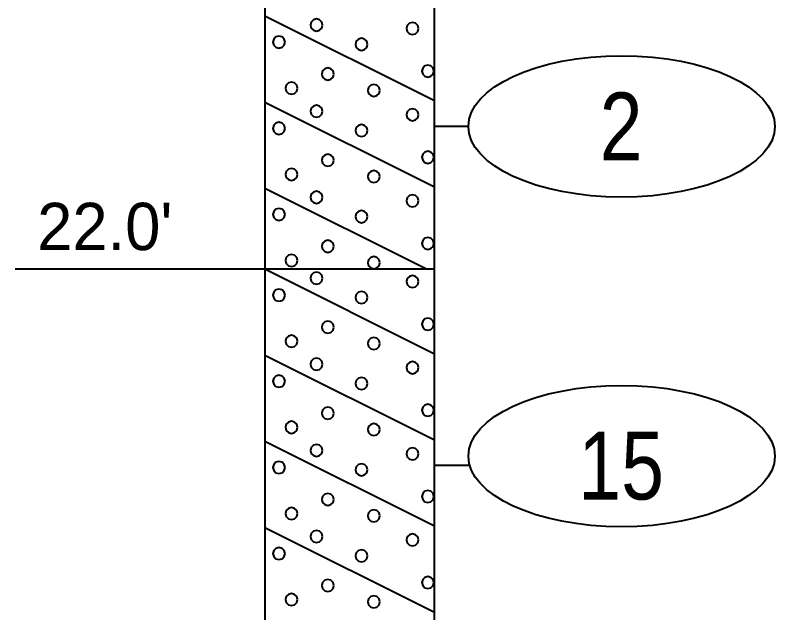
# Model space of a CAD drawing. Extents: x -76 to 974, y -1080 to -735.
# Drawn here: x -15.21 to -4.02, y -793.08 to -784.27 of the extents above; entities that cross this region are included whole.
import ezdxf
from ezdxf.enums import TextEntityAlignment as Align

# ---------------------------------------------------------------- set-up
doc = ezdxf.new("R2010")
doc.units = 0
doc.header["$LTSCALE"] = 0.36
doc.layers.add('27', color=7, linetype='Continuous', lineweight=40)

msp = doc.modelspace()

# ---------------------------------------------------------------- linework, layer by layer
at = {"layer": '27'}
for p, q in [((-11.5338, -783.0053), (-11.5338, -788.0053)), ((-9.0338, -788.0053), (-9.0338, -783.0053)), ((-11.5338, -784.2753), (-9.0338, -785.5253)), ((-11.5338, -785.5453), (-9.0338, -786.7953)), ((-8.5338, -785.9053), (-9.0338, -785.9053)), ((-11.5338, -786.8153), (-9.1538, -788.0053)), ((-15.2122, -788.0053), (-11.4448, -788.0053)), ((-11.5338, -788.0053), (-9.0338, -788.0053)), ((-11.5338, -788.0053), (-9.0338, -789.2553)), ((-11.5338, -788.0053), (-11.5338, -798.0053)), ((-9.0338, -798.0053), (-9.0338, -788.0053)), ((-11.5338, -789.2753), (-9.0338, -790.5253)), ((-11.5338, -790.5453), (-9.0338, -791.7953)), ((-8.5338, -790.9053), (-9.0338, -790.9053)), ((-11.5338, -791.8153), (-9.0338, -793.0653))]:
    msp.add_line(p, q, dxfattribs=at)
for points in [[(-10.6832, -784.4104), (-10.6951, -784.366), (-10.7276, -784.3334), (-10.7721, -784.3215), (-10.8165, -784.3334), (-10.849, -784.366), (-10.861, -784.4104), (-10.849, -784.4549), (-10.8165, -784.4874), (-10.7721, -784.4993), (-10.7276, -784.4874), (-10.6951, -784.4549)], [(-9.2682, -784.4613), (-9.2801, -784.4168), (-9.3127, -784.3843), (-9.3571, -784.3724), (-9.4016, -784.3843), (-9.4341, -784.4168), (-9.446, -784.4613), (-9.4341, -784.5057), (-9.4016, -784.5383), (-9.3571, -784.5502), (-9.3127, -784.5383), (-9.2801, -784.5057)], [(-11.2362, -784.6621), (-11.2481, -784.6177), (-11.2806, -784.5851), (-11.3251, -784.5732), (-11.3695, -784.5851), (-11.4021, -784.6177), (-11.414, -784.6621), (-11.4021, -784.7066), (-11.3695, -784.7391), (-11.3251, -784.751), (-11.2806, -784.7391), (-11.2481, -784.7066)], [(-10.0208, -784.6952), (-10.0327, -784.6507), (-10.0653, -784.6182), (-10.1097, -784.6063), (-10.1542, -784.6182), (-10.1867, -784.6507), (-10.1986, -784.6952), (-10.1867, -784.7396), (-10.1542, -784.7722), (-10.1097, -784.7841), (-10.0653, -784.7722), (-10.0327, -784.7396)], [(-10.5166, -785.1325), (-10.5285, -785.088), (-10.5611, -785.0555), (-10.6055, -785.0436), (-10.65, -785.0555), (-10.6825, -785.088), (-10.6944, -785.1325), (-10.6825, -785.1769), (-10.65, -785.2095), (-10.6055, -785.2214), (-10.5611, -785.2095), (-10.5285, -785.1769)], [(-9.0419, -785.0893), (-9.0539, -785.0448), (-9.0864, -785.0123), (-9.1308, -785.0004), (-9.1753, -785.0123), (-9.2078, -785.0448), (-9.2197, -785.0893), (-9.2078, -785.1337), (-9.1753, -785.1663), (-9.1308, -785.1782), (-9.0864, -785.1663), (-9.0539, -785.1337)], [(-11.0518, -785.341), (-11.0637, -785.2965), (-11.0963, -785.264), (-11.1407, -785.2521), (-11.1852, -785.264), (-11.2177, -785.2965), (-11.2296, -785.341), (-11.2177, -785.3854), (-11.1852, -785.418), (-11.1407, -785.4299), (-11.0963, -785.418), (-11.0637, -785.3854)], [(-9.839, -785.374), (-9.8509, -785.3296), (-9.8835, -785.297), (-9.9279, -785.2851), (-9.9724, -785.297), (-10.0049, -785.3296), (-10.0168, -785.374), (-10.0049, -785.4185), (-9.9724, -785.451), (-9.9279, -785.4629), (-9.8835, -785.451), (-9.8509, -785.4185)], [(-10.6831, -785.6816), (-10.695, -785.6372), (-10.7275, -785.6046), (-10.772, -785.5927), (-10.8164, -785.6046), (-10.849, -785.6372), (-10.8609, -785.6816), (-10.849, -785.7261), (-10.8164, -785.7586), (-10.772, -785.7705), (-10.7275, -785.7586), (-10.695, -785.7261)], [(-9.2682, -785.7325), (-9.2801, -785.6881), (-9.3127, -785.6555), (-9.3571, -785.6436), (-9.4016, -785.6555), (-9.4341, -785.6881), (-9.446, -785.7325), (-9.4341, -785.777), (-9.4016, -785.8095), (-9.3571, -785.8214), (-9.3127, -785.8095), (-9.2801, -785.777)], [(-11.2362, -785.9334), (-11.2481, -785.8889), (-11.2806, -785.8564), (-11.3251, -785.8445), (-11.3695, -785.8564), (-11.4021, -785.8889), (-11.414, -785.9334), (-11.4021, -785.9778), (-11.3695, -786.0104), (-11.3251, -786.0223), (-11.2806, -786.0104), (-11.2481, -785.9778)], [(-10.0208, -785.9664), (-10.0327, -785.922), (-10.0653, -785.8895), (-10.1097, -785.8775), (-10.1542, -785.8895), (-10.1867, -785.922), (-10.1986, -785.9664), (-10.1867, -786.0109), (-10.1542, -786.0434), (-10.1097, -786.0553), (-10.0653, -786.0434), (-10.0327, -786.0109)], [(-10.5166, -786.4038), (-10.5285, -786.3593), (-10.5611, -786.3268), (-10.6055, -786.3149), (-10.65, -786.3268), (-10.6825, -786.3593), (-10.6944, -786.4038), (-10.6825, -786.4482), (-10.65, -786.4808), (-10.6055, -786.4927), (-10.5611, -786.4808), (-10.5285, -786.4482)], [(-9.0419, -786.3605), (-9.0539, -786.3161), (-9.0864, -786.2836), (-9.1308, -786.2716), (-9.1753, -786.2836), (-9.2078, -786.3161), (-9.2197, -786.3605), (-9.2078, -786.405), (-9.1753, -786.4375), (-9.1308, -786.4494), (-9.0864, -786.4375), (-9.0539, -786.405)], [(-11.0518, -786.6123), (-11.0637, -786.5678), (-11.0963, -786.5353), (-11.1407, -786.5234), (-11.1852, -786.5353), (-11.2177, -786.5678), (-11.2296, -786.6123), (-11.2177, -786.6567), (-11.1852, -786.6892), (-11.1407, -786.7012), (-11.0963, -786.6892), (-11.0637, -786.6567)], [(-9.839, -786.6453), (-9.8509, -786.6009), (-9.8835, -786.5683), (-9.9279, -786.5564), (-9.9724, -786.5683), (-10.0049, -786.6009), (-10.0168, -786.6453), (-10.0049, -786.6898), (-9.9724, -786.7223), (-9.9279, -786.7342), (-9.8835, -786.7223), (-9.8509, -786.6898)], [(-10.6832, -786.9504), (-10.6951, -786.906), (-10.7276, -786.8734), (-10.7721, -786.8615), (-10.8165, -786.8734), (-10.849, -786.906), (-10.861, -786.9504), (-10.849, -786.9949), (-10.8165, -787.0274), (-10.7721, -787.0393), (-10.7276, -787.0274), (-10.6951, -786.9949)], [(-9.2682, -787.0013), (-9.2801, -786.9568), (-9.3127, -786.9243), (-9.3571, -786.9124), (-9.4016, -786.9243), (-9.4341, -786.9568), (-9.446, -787.0013), (-9.4341, -787.0457), (-9.4016, -787.0783), (-9.3571, -787.0902), (-9.3127, -787.0783), (-9.2801, -787.0457)], [(-11.2362, -787.2021), (-11.2481, -787.1577), (-11.2806, -787.1251), (-11.3251, -787.1132), (-11.3695, -787.1251), (-11.4021, -787.1577), (-11.414, -787.2021), (-11.4021, -787.2466), (-11.3695, -787.2791), (-11.3251, -787.291), (-11.2806, -787.2791), (-11.2481, -787.2466)], [(-10.0208, -787.2352), (-10.0327, -787.1907), (-10.0653, -787.1582), (-10.1097, -787.1463), (-10.1542, -787.1582), (-10.1867, -787.1907), (-10.1986, -787.2352), (-10.1867, -787.2796), (-10.1542, -787.3122), (-10.1097, -787.3241), (-10.0653, -787.3122), (-10.0327, -787.2796)], [(-9.0419, -787.6293), (-9.0539, -787.5848), (-9.0864, -787.5523), (-9.1308, -787.5404), (-9.1753, -787.5523), (-9.2078, -787.5848), (-9.2197, -787.6293), (-9.2078, -787.6737), (-9.1753, -787.7063), (-9.1308, -787.7182), (-9.0864, -787.7063), (-9.0539, -787.6737)], [(-10.5166, -787.6725), (-10.5285, -787.628), (-10.5611, -787.5955), (-10.6055, -787.5836), (-10.65, -787.5955), (-10.6825, -787.628), (-10.6944, -787.6725), (-10.6825, -787.7169), (-10.65, -787.7495), (-10.6055, -787.7614), (-10.5611, -787.7495), (-10.5285, -787.7169)], [(-11.0518, -787.881), (-11.0637, -787.8365), (-11.0963, -787.804), (-11.1407, -787.7921), (-11.1852, -787.804), (-11.2177, -787.8365), (-11.2296, -787.881), (-11.2177, -787.9254), (-11.1852, -787.958), (-11.1407, -787.9699), (-11.0963, -787.958), (-11.0637, -787.9254)], [(-9.839, -787.914), (-9.8509, -787.8696), (-9.8835, -787.837), (-9.9279, -787.8251), (-9.9724, -787.837), (-10.0049, -787.8696), (-10.0168, -787.914), (-10.0049, -787.9585), (-9.9724, -787.991), (-9.9279, -788.0029), (-9.8835, -787.991), (-9.8509, -787.9585)], [(-10.6831, -788.1416), (-10.695, -788.0972), (-10.7275, -788.0646), (-10.772, -788.0527), (-10.8164, -788.0646), (-10.849, -788.0972), (-10.8609, -788.1416), (-10.849, -788.1861), (-10.8164, -788.2186), (-10.772, -788.2305), (-10.7275, -788.2186), (-10.695, -788.1861)], [(-9.2682, -788.1925), (-9.2801, -788.1481), (-9.3127, -788.1155), (-9.3571, -788.1036), (-9.4016, -788.1155), (-9.4341, -788.1481), (-9.446, -788.1925), (-9.4341, -788.237), (-9.4016, -788.2695), (-9.3571, -788.2814), (-9.3127, -788.2695), (-9.2801, -788.237)], [(-11.2362, -788.3934), (-11.2481, -788.3489), (-11.2806, -788.3164), (-11.3251, -788.3045), (-11.3695, -788.3164), (-11.4021, -788.3489), (-11.414, -788.3934), (-11.4021, -788.4378), (-11.3695, -788.4704), (-11.3251, -788.4823), (-11.2806, -788.4704), (-11.2481, -788.4378)], [(-10.0208, -788.4264), (-10.0327, -788.382), (-10.0653, -788.3495), (-10.1097, -788.3375), (-10.1542, -788.3495), (-10.1867, -788.382), (-10.1986, -788.4264), (-10.1867, -788.4709), (-10.1542, -788.5034), (-10.1097, -788.5153), (-10.0653, -788.5034), (-10.0327, -788.4709)], [(-10.5166, -788.8638), (-10.5285, -788.8193), (-10.5611, -788.7868), (-10.6055, -788.7749), (-10.65, -788.7868), (-10.6825, -788.8193), (-10.6944, -788.8638), (-10.6825, -788.9082), (-10.65, -788.9408), (-10.6055, -788.9527), (-10.5611, -788.9408), (-10.5285, -788.9082)], [(-9.0419, -788.8205), (-9.0539, -788.7761), (-9.0864, -788.7436), (-9.1308, -788.7316), (-9.1753, -788.7436), (-9.2078, -788.7761), (-9.2197, -788.8205), (-9.2078, -788.865), (-9.1753, -788.8975), (-9.1308, -788.9094), (-9.0864, -788.8975), (-9.0539, -788.865)], [(-11.0518, -789.0723), (-11.0637, -789.0278), (-11.0963, -788.9953), (-11.1407, -788.9834), (-11.1852, -788.9953), (-11.2177, -789.0278), (-11.2296, -789.0723), (-11.2177, -789.1167), (-11.1852, -789.1492), (-11.1407, -789.1612), (-11.0963, -789.1492), (-11.0637, -789.1167)], [(-9.839, -789.1053), (-9.8509, -789.0609), (-9.8835, -789.0283), (-9.9279, -789.0164), (-9.9724, -789.0283), (-10.0049, -789.0609), (-10.0168, -789.1053), (-10.0049, -789.1498), (-9.9724, -789.1823), (-9.9279, -789.1942), (-9.8835, -789.1823), (-9.8509, -789.1498)], [(-10.6832, -789.4104), (-10.6951, -789.366), (-10.7276, -789.3334), (-10.7721, -789.3215), (-10.8165, -789.3334), (-10.849, -789.366), (-10.861, -789.4104), (-10.849, -789.4549), (-10.8165, -789.4874), (-10.7721, -789.4993), (-10.7276, -789.4874), (-10.6951, -789.4549)], [(-9.2682, -789.4613), (-9.2801, -789.4168), (-9.3127, -789.3843), (-9.3571, -789.3724), (-9.4016, -789.3843), (-9.4341, -789.4168), (-9.446, -789.4613), (-9.4341, -789.5057), (-9.4016, -789.5383), (-9.3571, -789.5502), (-9.3127, -789.5383), (-9.2801, -789.5057)], [(-11.2362, -789.6621), (-11.2481, -789.6177), (-11.2806, -789.5851), (-11.3251, -789.5732), (-11.3695, -789.5851), (-11.4021, -789.6177), (-11.414, -789.6621), (-11.4021, -789.7066), (-11.3695, -789.7391), (-11.3251, -789.751), (-11.2806, -789.7391), (-11.2481, -789.7066)], [(-10.0208, -789.6952), (-10.0327, -789.6507), (-10.0653, -789.6182), (-10.1097, -789.6063), (-10.1542, -789.6182), (-10.1867, -789.6507), (-10.1986, -789.6952), (-10.1867, -789.7396), (-10.1542, -789.7722), (-10.1097, -789.7841), (-10.0653, -789.7722), (-10.0327, -789.7396)], [(-9.0419, -790.0893), (-9.0539, -790.0448), (-9.0864, -790.0123), (-9.1308, -790.0004), (-9.1753, -790.0123), (-9.2078, -790.0448), (-9.2197, -790.0893), (-9.2078, -790.1337), (-9.1753, -790.1663), (-9.1308, -790.1782), (-9.0864, -790.1663), (-9.0539, -790.1337)], [(-10.5166, -790.1325), (-10.5285, -790.088), (-10.5611, -790.0555), (-10.6055, -790.0436), (-10.65, -790.0555), (-10.6825, -790.088), (-10.6944, -790.1325), (-10.6825, -790.1769), (-10.65, -790.2095), (-10.6055, -790.2214), (-10.5611, -790.2095), (-10.5285, -790.1769)], [(-11.0518, -790.341), (-11.0637, -790.2965), (-11.0963, -790.264), (-11.1407, -790.2521), (-11.1852, -790.264), (-11.2177, -790.2965), (-11.2296, -790.341), (-11.2177, -790.3854), (-11.1852, -790.418), (-11.1407, -790.4299), (-11.0963, -790.418), (-11.0637, -790.3854)], [(-9.839, -790.374), (-9.8509, -790.3296), (-9.8835, -790.297), (-9.9279, -790.2851), (-9.9724, -790.297), (-10.0049, -790.3296), (-10.0168, -790.374), (-10.0049, -790.4185), (-9.9724, -790.451), (-9.9279, -790.4629), (-9.8835, -790.451), (-9.8509, -790.4185)], [(-10.6831, -790.6816), (-10.695, -790.6372), (-10.7275, -790.6046), (-10.772, -790.5927), (-10.8164, -790.6046), (-10.849, -790.6372), (-10.8609, -790.6816), (-10.849, -790.7261), (-10.8164, -790.7586), (-10.772, -790.7705), (-10.7275, -790.7586), (-10.695, -790.7261)], [(-9.2682, -790.7325), (-9.2801, -790.6881), (-9.3127, -790.6555), (-9.3571, -790.6436), (-9.4016, -790.6555), (-9.4341, -790.6881), (-9.446, -790.7325), (-9.4341, -790.777), (-9.4016, -790.8095), (-9.3571, -790.8214), (-9.3127, -790.8095), (-9.2801, -790.777)], [(-11.2362, -790.9334), (-11.2481, -790.8889), (-11.2806, -790.8564), (-11.3251, -790.8445), (-11.3695, -790.8564), (-11.4021, -790.8889), (-11.414, -790.9334), (-11.4021, -790.9778), (-11.3695, -791.0104), (-11.3251, -791.0223), (-11.2806, -791.0104), (-11.2481, -790.9778)], [(-10.0208, -790.9664), (-10.0327, -790.922), (-10.0653, -790.8895), (-10.1097, -790.8775), (-10.1542, -790.8895), (-10.1867, -790.922), (-10.1986, -790.9664), (-10.1867, -791.0109), (-10.1542, -791.0434), (-10.1097, -791.0553), (-10.0653, -791.0434), (-10.0327, -791.0109)], [(-10.5166, -791.4038), (-10.5285, -791.3593), (-10.5611, -791.3268), (-10.6055, -791.3149), (-10.65, -791.3268), (-10.6825, -791.3593), (-10.6944, -791.4038), (-10.6825, -791.4482), (-10.65, -791.4808), (-10.6055, -791.4927), (-10.5611, -791.4808), (-10.5285, -791.4482)], [(-9.0419, -791.3605), (-9.0539, -791.3161), (-9.0864, -791.2836), (-9.1308, -791.2716), (-9.1753, -791.2836), (-9.2078, -791.3161), (-9.2197, -791.3605), (-9.2078, -791.405), (-9.1753, -791.4375), (-9.1308, -791.4494), (-9.0864, -791.4375), (-9.0539, -791.405)], [(-11.0518, -791.6123), (-11.0637, -791.5678), (-11.0963, -791.5353), (-11.1407, -791.5234), (-11.1852, -791.5353), (-11.2177, -791.5678), (-11.2296, -791.6123), (-11.2177, -791.6567), (-11.1852, -791.6892), (-11.1407, -791.7012), (-11.0963, -791.6892), (-11.0637, -791.6567)], [(-9.839, -791.6453), (-9.8509, -791.6009), (-9.8835, -791.5683), (-9.9279, -791.5564), (-9.9724, -791.5683), (-10.0049, -791.6009), (-10.0168, -791.6453), (-10.0049, -791.6898), (-9.9724, -791.7223), (-9.9279, -791.7342), (-9.8835, -791.7223), (-9.8509, -791.6898)], [(-10.6832, -791.9504), (-10.6951, -791.906), (-10.7276, -791.8734), (-10.7721, -791.8615), (-10.8165, -791.8734), (-10.849, -791.906), (-10.861, -791.9504), (-10.849, -791.9949), (-10.8165, -792.0274), (-10.7721, -792.0393), (-10.7276, -792.0274), (-10.6951, -791.9949)], [(-9.2682, -792.0013), (-9.2801, -791.9568), (-9.3127, -791.9243), (-9.3571, -791.9124), (-9.4016, -791.9243), (-9.4341, -791.9568), (-9.446, -792.0013), (-9.4341, -792.0457), (-9.4016, -792.0783), (-9.3571, -792.0902), (-9.3127, -792.0783), (-9.2801, -792.0457)], [(-11.2362, -792.2021), (-11.2481, -792.1577), (-11.2806, -792.1251), (-11.3251, -792.1132), (-11.3695, -792.1251), (-11.4021, -792.1577), (-11.414, -792.2021), (-11.4021, -792.2466), (-11.3695, -792.2791), (-11.3251, -792.291), (-11.2806, -792.2791), (-11.2481, -792.2466)], [(-10.0208, -792.2352), (-10.0327, -792.1907), (-10.0653, -792.1582), (-10.1097, -792.1463), (-10.1542, -792.1582), (-10.1867, -792.1907), (-10.1986, -792.2352), (-10.1867, -792.2796), (-10.1542, -792.3122), (-10.1097, -792.3241), (-10.0653, -792.3122), (-10.0327, -792.2796)], [(-10.5166, -792.6725), (-10.5285, -792.628), (-10.5611, -792.5955), (-10.6055, -792.5836), (-10.65, -792.5955), (-10.6825, -792.628), (-10.6944, -792.6725), (-10.6825, -792.7169), (-10.65, -792.7495), (-10.6055, -792.7614), (-10.5611, -792.7495), (-10.5285, -792.7169)], [(-9.0419, -792.6293), (-9.0539, -792.5848), (-9.0864, -792.5523), (-9.1308, -792.5404), (-9.1753, -792.5523), (-9.2078, -792.5848), (-9.2197, -792.6293), (-9.2078, -792.6737), (-9.1753, -792.7063), (-9.1308, -792.7182), (-9.0864, -792.7063), (-9.0539, -792.6737)], [(-11.0518, -792.881), (-11.0637, -792.8365), (-11.0963, -792.804), (-11.1407, -792.7921), (-11.1852, -792.804), (-11.2177, -792.8365), (-11.2296, -792.881), (-11.2177, -792.9254), (-11.1852, -792.958), (-11.1407, -792.9699), (-11.0963, -792.958), (-11.0637, -792.9254)], [(-9.839, -792.914), (-9.8509, -792.8696), (-9.8835, -792.837), (-9.9279, -792.8251), (-9.9724, -792.837), (-10.0049, -792.8696), (-10.0168, -792.914), (-10.0049, -792.9585), (-9.9724, -792.991), (-9.9279, -793.0029), (-9.8835, -792.991), (-9.8509, -792.9585)]]:
    msp.add_lwpolyline(points, close=True, dxfattribs=at)
for centre in [(-6.2764, -785.9053), (-6.2764, -790.7655)]:
    msp.add_ellipse(centre, major_axis=(2.2574, 0), ratio=0.461538, dxfattribs=at)

# ---------------------------------------------------------------- texts
at = {"layer": '27', "width": 0.85}
for s, p in [('2', (-6.2837, -786.4052)), ('15', (-6.2838, -791.4052))]:
    msp.add_text(s, height=1, dxfattribs=at).set_placement(p, align=Align.CENTER)
at = {"layer": '27'}
msp.add_text("22.0'", height=0.6976, dxfattribs=at).set_placement((-14.8882, -787.7289))

doc.saveas('drawing.dxf')
